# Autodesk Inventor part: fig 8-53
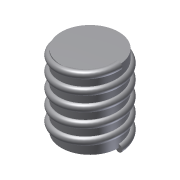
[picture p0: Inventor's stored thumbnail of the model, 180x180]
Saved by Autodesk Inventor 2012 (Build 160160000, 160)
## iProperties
Shininess: 77.0
Length Units: 11269
Angle Units: 11279
Time Units: 11290
Mass Units: 11283
Length Display Precision: 3
Angle Display Precision: 2
Created: 2002-01
Part Number: fig 8-53
Document SubType Name: Modeling
Designer: CADSoft
Density: 1 g/cm^3
Material: Default
Density: 0.0
Volumn: 0.0
Area: 0.0
PropertySet Name: Model Information
Control State: 0
Master: False
Checked Out: False
Author: CADSoft
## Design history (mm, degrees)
sketch "Sketch4"
  geometry: C1 r 20 at (0, 0)
  constraints: 1 centre point
  dimensions: "d44" = 40 diameter of C1
sketch "Sketch2"
  geometry: C1 r 2.5 at (-20, -0.092); 1 further point
  constraints: 1 centre point, 1 other
  dimensions: "d0" = 5 diameter of C1; "d43" = 20 horizontal distance of C1.centre point (0, 0)
extrude "Extrusion2" join sketch "Sketch4" distance "d45" = 50; taper "d46" = 0 deg
coil "Coil6" pitch "d47" = 10; turns "d49" = 5; dims "d48" = 10, "d50" = 0, angle "d51" = 90 deg, angle "d52" = 90 deg, "d53" = 0, "d54" = 0
body "Solid1"
